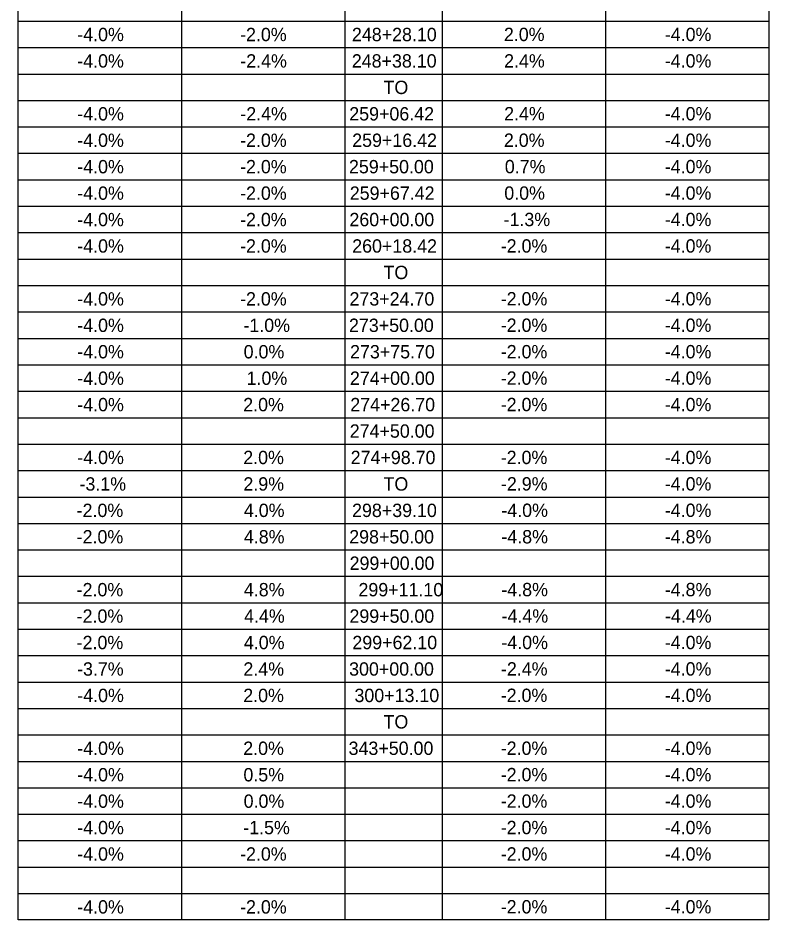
# Model space of a CAD drawing. Extents: x -15319374 to 1762012, y 465773 to 3693661.
# Drawn here: x -15315612.5 to -15315443.6, y 3692070 to 3692272.7 of the extents above; entities that cross this region are included whole.
import ezdxf

# ---------------------------------------------------------------- set-up
doc = ezdxf.new("R2010")
doc.units = 0
doc.layers.add('BORDER', color=7, linetype='Continuous')
doc.layers.add('DIMENSIONS', color=7, linetype='Continuous')

msp = doc.modelspace()

# ---------------------------------------------------------------- linework, layer by layer
at = {"layer": 'BORDER'}
for p, q in [((-15315575.73, 3692474.03), (-15315575.73, 3692069.99)), ((-15315538.96, 3692474.03), (-15315538.96, 3692069.99)), ((-15315517.09, 3692474.03), (-15315517.09, 3692069.99)), ((-15315480.32, 3692474.03), (-15315480.32, 3692069.99)), ((-15315612.5, 3692272.04), (-15315443.55, 3692272.04)), ((-15315612.5, 3692266.1), (-15315443.55, 3692266.1)), ((-15315612.5, 3692260.16), (-15315443.55, 3692260.16)), ((-15315612.5, 3692254.22), (-15315443.55, 3692254.22)), ((-15315612.5, 3692248.27), (-15315443.55, 3692248.27)), ((-15315612.5, 3692242.33), (-15315443.55, 3692242.33)), ((-15315612.5, 3692236.39), (-15315443.55, 3692236.39)), ((-15315612.5, 3692230.44), (-15315443.55, 3692230.44)), ((-15315612.5, 3692224.5), (-15315443.55, 3692224.5)), ((-15315612.5, 3692218.56), (-15315443.55, 3692218.56)), ((-15315612.5, 3692212.62), (-15315443.55, 3692212.62)), ((-15315612.5, 3692206.67), (-15315443.55, 3692206.67)), ((-15315612.5, 3692200.73), (-15315443.55, 3692200.73)), ((-15315612.5, 3692194.79), (-15315443.55, 3692194.79)), ((-15315612.5, 3692188.85), (-15315443.55, 3692188.85)), ((-15315612.5, 3692182.9), (-15315443.55, 3692182.9)), ((-15315612.5, 3692176.96), (-15315443.55, 3692176.96)), ((-15315612.5, 3692171.02), (-15315443.55, 3692171.02)), ((-15315612.5, 3692165.07), (-15315443.55, 3692165.07)), ((-15315612.5, 3692159.13), (-15315443.55, 3692159.13)), ((-15315612.5, 3692153.19), (-15315443.55, 3692153.19)), ((-15315612.5, 3692147.25), (-15315443.55, 3692147.25)), ((-15315612.5, 3692141.3), (-15315443.55, 3692141.3)), ((-15315612.5, 3692135.36), (-15315443.55, 3692135.36)), ((-15315612.5, 3692129.42), (-15315443.55, 3692129.42)), ((-15315612.5, 3692123.48), (-15315443.55, 3692123.48)), ((-15315612.5, 3692117.53), (-15315443.55, 3692117.53)), ((-15315612.5, 3692111.59), (-15315443.55, 3692111.59)), ((-15315612.5, 3692105.65), (-15315443.55, 3692105.65)), ((-15315612.5, 3692099.71), (-15315443.55, 3692099.71)), ((-15315612.5, 3692093.76), (-15315443.55, 3692093.76)), ((-15315612.5, 3692087.82), (-15315443.55, 3692087.82)), ((-15315612.5, 3692081.88), (-15315443.55, 3692081.88)), ((-15315612.5, 3692075.93), (-15315443.55, 3692075.93))]:
    msp.add_line(p, q, dxfattribs=at)
msp.add_lwpolyline([(-15315612.5, 3692474.03), (-15315443.55, 3692474.03), (-15315443.55, 3692069.99), (-15315612.5, 3692069.99)], close=True, dxfattribs=at)

# ---------------------------------------------------------------- texts
at = {"layer": 'DIMENSIONS'}
for s, p in [('-4.0%', (-15315599.17, 3692267.54)), ('-2.0%', (-15315562.54, 3692267.54)), ('248+28.10', (-15315537.38, 3692267.54)), ('2.0%', (-15315503.19, 3692267.56)), ('-4.0%', (-15315466.99, 3692267.56)), ('-4.0%', (-15315599.17, 3692261.6)), ('-2.4%', (-15315562.49, 3692261.6)), ('248+38.10', (-15315537.4, 3692261.6)), ('2.4%', (-15315503.14, 3692261.61)), ('-4.0%', (-15315466.99, 3692261.61)), ('TO', (-15315530.27, 3692255.65)), ('-4.0%', (-15315599.17, 3692249.71)), ('-2.4%', (-15315562.49, 3692249.71)), ('259+06.42', (-15315537.98, 3692249.71)), ('2.4%', (-15315503.14, 3692249.73)), ('-4.0%', (-15315466.99, 3692249.73)), ('-4.0%', (-15315599.17, 3692243.77)), ('-2.0%', (-15315562.54, 3692243.77)), ('259+16.42', (-15315537.32, 3692243.77)), ('2.0%', (-15315503.19, 3692243.78)), ('-4.0%', (-15315466.99, 3692243.78)), ('-4.0%', (-15315599.17, 3692237.83)), ('-2.0%', (-15315562.54, 3692237.83)), ('259+50.00', (-15315538.04, 3692237.83)), ('0.7%', (-15315502.98, 3692237.84)), ('-4.0%', (-15315466.99, 3692237.84)), ('-4.0%', (-15315599.17, 3692231.88)), ('-2.0%', (-15315562.54, 3692231.88)), ('259+67.42', (-15315537.86, 3692231.88)), ('0.0%', (-15315503.1, 3692231.9)), ('-4.0%', (-15315466.99, 3692231.9)), ('-4.0%', (-15315599.17, 3692225.94)), ('-2.0%', (-15315562.54, 3692225.94)), ('260+00.00', (-15315537.94, 3692225.94)), ('-1.3%', (-15315503.26, 3692225.96)), ('-4.0%', (-15315466.99, 3692225.96)), ('-4.0%', (-15315599.17, 3692220)), ('-2.0%', (-15315562.54, 3692220)), ('260+18.42', (-15315537.32, 3692220)), ('-2.0%', (-15315503.9, 3692220.01)), ('-4.0%', (-15315466.99, 3692220.01)), ('TO', (-15315530.27, 3692214.05)), ('-4.0%', (-15315599.17, 3692208.11)), ('-2.0%', (-15315562.54, 3692208.11)), ('273+24.70', (-15315537.92, 3692208.11)), ('-2.0%', (-15315503.9, 3692208.13)), ('-4.0%', (-15315466.99, 3692208.13)), ('-4.0%', (-15315599.17, 3692202.17)), ('-1.0%', (-15315561.79, 3692202.17)), ('273+50.00', (-15315538.04, 3692202.17)), ('-2.0%', (-15315503.9, 3692202.19)), ('-4.0%', (-15315466.99, 3692202.19)), ('-4.0%', (-15315599.17, 3692196.23)), ('0.0%', (-15315561.74, 3692196.23)), ('273+75.70', (-15315537.8, 3692196.23)), ('-2.0%', (-15315503.9, 3692196.24)), ('-4.0%', (-15315466.99, 3692196.24)), ('-4.0%', (-15315599.17, 3692190.28)), ('1.0%', (-15315561.08, 3692190.28)), ('274+00.00', (-15315537.83, 3692190.28)), ('-2.0%', (-15315503.9, 3692190.3)), ('-4.0%', (-15315466.99, 3692190.3)), ('-4.0%', (-15315599.17, 3692184.34)), ('2.0%', (-15315561.83, 3692184.34)), ('274+26.70', (-15315537.75, 3692184.34)), ('-2.0%', (-15315503.9, 3692184.36)), ('-4.0%', (-15315466.99, 3692184.36)), ('274+50.00', (-15315537.87, 3692178.4)), ('-4.0%', (-15315599.17, 3692172.46)), ('2.0%', (-15315561.83, 3692172.46)), ('274+98.70', (-15315537.66, 3692172.46)), ('-2.0%', (-15315503.9, 3692172.47)), ('-4.0%', (-15315466.99, 3692172.47)), ('-3.1%', (-15315598.67, 3692166.51)), ('2.9%', (-15315561.79, 3692166.51)), ('TO', (-15315530.27, 3692166.51)), ('-2.9%', (-15315503.85, 3692166.53)), ('-4.0%', (-15315466.99, 3692166.53)), ('-2.0%', (-15315599.31, 3692160.57)), ('4.0%', (-15315561.69, 3692160.57)), ('298+39.10', (-15315537.35, 3692160.57)), ('-4.0%', (-15315503.76, 3692160.59)), ('-4.0%', (-15315466.99, 3692160.59)), ('-2.0%', (-15315599.31, 3692154.63)), ('4.8%', (-15315561.69, 3692154.63)), ('298+50.00', (-15315537.99, 3692154.63)), ('-4.8%', (-15315503.76, 3692154.64)), ('-4.8%', (-15315466.99, 3692154.64)), ('299+00.00', (-15315537.9, 3692148.69)), ('-2.0%', (-15315599.31, 3692142.74)), ('4.8%', (-15315561.69, 3692142.74)), ('299+11.10', (-15315535.91, 3692142.74)), ('-4.8%', (-15315503.76, 3692142.76)), ('-4.8%', (-15315466.99, 3692142.76)), ('-2.0%', (-15315599.31, 3692136.8)), ('4.4%', (-15315561.64, 3692136.8)), ('299+50.00', (-15315537.94, 3692136.8)), ('-4.4%', (-15315503.71, 3692136.82)), ('-4.4%', (-15315466.94, 3692136.82)), ('-2.0%', (-15315599.31, 3692130.86)), ('4.0%', (-15315561.69, 3692130.86)), ('299+62.10', (-15315537.28, 3692130.86)), ('-4.0%', (-15315503.76, 3692130.87)), ('-4.0%', (-15315466.99, 3692130.87)), ('-3.7%', (-15315599.22, 3692124.91)), ('2.4%', (-15315561.79, 3692124.91)), ('300+00.00', (-15315538.01, 3692124.91)), ('-2.4%', (-15315503.85, 3692124.93)), ('-4.0%', (-15315466.99, 3692124.93)), ('-4.0%', (-15315599.17, 3692118.97)), ('2.0%', (-15315561.83, 3692118.97)), ('300+13.10', (-15315536.81, 3692118.97)), ('-2.0%', (-15315503.9, 3692118.99)), ('-4.0%', (-15315466.99, 3692118.99)), ('TO', (-15315530.27, 3692113.03)), ('-4.0%', (-15315599.17, 3692107.09)), ('2.0%', (-15315561.83, 3692107.09)), ('343+50.00', (-15315538.13, 3692107.09)), ('-2.0%', (-15315503.9, 3692107.1)), ('-4.0%', (-15315466.99, 3692107.1)), ('-4.0%', (-15315599.17, 3692101.14)), ('0.5%', (-15315561.79, 3692101.14)), ('-2.0%', (-15315503.9, 3692101.16)), ('-4.0%', (-15315466.99, 3692101.16)), ('-4.0%', (-15315599.17, 3692095.2)), ('0.0%', (-15315561.74, 3692095.2)), ('-2.0%', (-15315503.9, 3692095.22)), ('-4.0%', (-15315466.99, 3692095.22)), ('-4.0%', (-15315599.17, 3692089.26)), ('-1.5%', (-15315561.83, 3692089.26)), ('-2.0%', (-15315503.9, 3692089.27)), ('-4.0%', (-15315466.99, 3692089.27)), ('-4.0%', (-15315599.17, 3692083.32)), ('-2.0%', (-15315562.54, 3692083.32)), ('-2.0%', (-15315503.9, 3692083.33)), ('-4.0%', (-15315466.99, 3692083.33)), ('-4.0%', (-15315599.17, 3692071.43)), ('-2.0%', (-15315562.54, 3692071.43)), ('-2.0%', (-15315503.9, 3692071.45)), ('-4.0%', (-15315466.99, 3692071.45))]:
    msp.add_text(s, height=3, dxfattribs=at).set_placement(p)

doc.saveas('drawing.dxf')
